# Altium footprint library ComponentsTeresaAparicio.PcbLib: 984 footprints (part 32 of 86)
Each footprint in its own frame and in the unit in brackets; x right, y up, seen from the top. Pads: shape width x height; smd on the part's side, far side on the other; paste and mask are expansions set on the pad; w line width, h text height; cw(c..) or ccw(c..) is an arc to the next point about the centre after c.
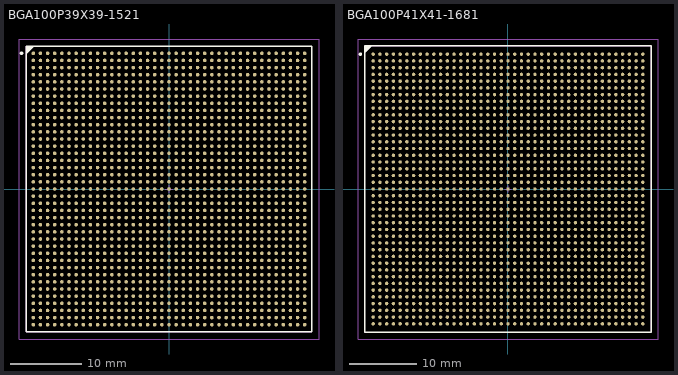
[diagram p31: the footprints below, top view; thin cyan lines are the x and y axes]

## BGA100P39X39-1521 [mm] "BGA, 1521-Leads, Body 40x40mm, Pitch 1mm"
height 3.5
pads (1521):
  round 0.5 smd: A1(-19,19) A2(-18,19) A3(-17,19) A4(-16,19) A5(-15,19) A6(-14,19) A7(-13,19) A8(-12,19) A9(-11,19) A10(-10,19) A11(-9,19) A12(-8,19) A13(-7,19) A14(-6,19) A15(-5,19) A16(-4,19) A17(-3,19) A18(-2,19) A19(-1,19) A20(0,19) A21(1,19) A22(2,19) A23(3,19) A24(4,19) A25(5,19) A26(6,19) A27(7,19) A28(8,19) A29(9,19) A30(10,19) A31(11,19) A32(12,19) A33(13,19) A34(14,19) A35(15,19) A36(16,19) A37(17,19) A38(18,19) A39(19,19) AA1(-19,-1) AA2(-18,-1) AA3(-17,-1) AA4(-16,-1) AA5(-15,-1) AA6(-14,-1) AA7(-13,-1) AA8(-12,-1) AA9(-11,-1) AA10(-10,-1) AA11(-9,-1) AA12(-8,-1) AA13(-7,-1) AA14(-6,-1) AA15(-5,-1) AA16(-4,-1) AA17(-3,-1) AA18(-2,-1) AA19(-1,-1) AA20(0,-1) AA21(1,-1) AA22(2,-1) AA23(3,-1) AA24(4,-1) AA25(5,-1) AA26(6,-1) AA27(7,-1) AA28(8,-1) AA29(9,-1) AA30(10,-1) AA31(11,-1) AA32(12,-1) AA33(13,-1) AA34(14,-1) AA35(15,-1) AA36(16,-1) AA37(17,-1) AA38(18,-1) AA39(19,-1) AB1(-19,-2) AB2(-18,-2) AB3(-17,-2) AB4(-16,-2) AB5(-15,-2) AB6(-14,-2) AB7(-13,-2) AB8(-12,-2) AB9(-11,-2) AB10(-10,-2) AB11(-9,-2) AB12(-8,-2) AB13(-7,-2) AB14(-6,-2) AB15(-5,-2) AB16(-4,-2) AB17(-3,-2) AB18(-2,-2) AB19(-1,-2) AB20(0,-2) AB21(1,-2) AB22(2,-2) AB23(3,-2) AB24(4,-2) AB25(5,-2) AB26(6,-2) AB27(7,-2) AB28(8,-2) AB29(9,-2) AB30(10,-2) AB31(11,-2) AB32(12,-2) AB33(13,-2) AB34(14,-2) AB35(15,-2) AB36(16,-2) AB37(17,-2) AB38(18,-2) AB39(19,-2) AC1(-19,-3) AC2(-18,-3) AC3(-17,-3) AC4(-16,-3) AC5(-15,-3) AC6(-14,-3) AC7(-13,-3) AC8(-12,-3) AC9(-11,-3) AC10(-10,-3) AC11(-9,-3) AC12(-8,-3) AC13(-7,-3) AC14(-6,-3) AC15(-5,-3) AC16(-4,-3) AC17(-3,-3) AC18(-2,-3) AC19(-1,-3) AC20(0,-3) AC21(1,-3) AC22(2,-3) AC23(3,-3) AC24(4,-3) AC25(5,-3) AC26(6,-3) AC27(7,-3) AC28(8,-3) AC29(9,-3) AC30(10,-3) AC31(11,-3) AC32(12,-3) AC33(13,-3) AC34(14,-3) AC35(15,-3) AC36(16,-3) AC37(17,-3) AC38(18,-3) AC39(19,-3) AD1(-19,-4) AD2(-18,-4) AD3(-17,-4) AD4(-16,-4) AD5(-15,-4) AD6(-14,-4) AD7(-13,-4) AD8(-12,-4) AD9(-11,-4) AD10(-10,-4) AD11(-9,-4) AD12(-8,-4) AD13(-7,-4) AD14(-6,-4) AD15(-5,-4) AD16(-4,-4) AD17(-3,-4) AD18(-2,-4) AD19(-1,-4) AD20(0,-4) AD21(1,-4) AD22(2,-4) AD23(3,-4) AD24(4,-4) AD25(5,-4) AD26(6,-4) AD27(7,-4) AD28(8,-4) AD29(9,-4) AD30(10,-4) AD31(11,-4) AD32(12,-4) AD33(13,-4) AD34(14,-4) AD35(15,-4) AD36(16,-4) AD37(17,-4) AD38(18,-4) AD39(19,-4) AE1(-19,-5) AE2(-18,-5) AE3(-17,-5) AE4(-16,-5) AE5(-15,-5) AE6(-14,-5) AE7(-13,-5) AE8(-12,-5) AE9(-11,-5) AE10(-10,-5) AE11(-9,-5) AE12(-8,-5) AE13(-7,-5) AE14(-6,-5) AE15(-5,-5) AE16(-4,-5) AE17(-3,-5) AE18(-2,-5) AE19(-1,-5) AE20(0,-5) AE21(1,-5) AE22(2,-5) AE23(3,-5) AE24(4,-5) AE25(5,-5) AE26(6,-5) AE27(7,-5) AE28(8,-5) AE29(9,-5) AE30(10,-5) AE31(11,-5) AE32(12,-5) AE33(13,-5) AE34(14,-5) AE35(15,-5) AE36(16,-5) AE37(17,-5) AE38(18,-5) AE39(19,-5) AF1(-19,-6) AF2(-18,-6) AF3(-17,-6) AF4(-16,-6) AF5(-15,-6) AF6(-14,-6) AF7(-13,-6) AF8(-12,-6) AF9(-11,-6) AF10(-10,-6) AF11(-9,-6) AF12(-8,-6) AF13(-7,-6) AF14(-6,-6) AF15(-5,-6) AF16(-4,-6) AF17(-3,-6) AF18(-2,-6) AF19(-1,-6) AF20(0,-6) AF21(1,-6) AF22(2,-6) AF23(3,-6) AF24(4,-6) AF25(5,-6) AF26(6,-6) AF27(7,-6) AF28(8,-6) AF29(9,-6) AF30(10,-6) AF31(11,-6) AF32(12,-6) AF33(13,-6) AF34(14,-6) AF35(15,-6) AF36(16,-6) AF37(17,-6) AF38(18,-6) AF39(19,-6) AG1(-19,-7) AG2(-18,-7) AG3(-17,-7) AG4(-16,-7) AG5(-15,-7) AG6(-14,-7) AG7(-13,-7) AG8(-12,-7) AG9(-11,-7) AG10(-10,-7) AG11(-9,-7) AG12(-8,-7) AG13(-7,-7) AG14(-6,-7) AG15(-5,-7) AG16(-4,-7) AG17(-3,-7) AG18(-2,-7) AG19(-1,-7) AG20(0,-7) AG21(1,-7) AG22(2,-7) AG23(3,-7) AG24(4,-7) AG25(5,-7) AG26(6,-7) AG27(7,-7) AG28(8,-7) AG29(9,-7) AG30(10,-7) AG31(11,-7) AG32(12,-7) AG33(13,-7) AG34(14,-7) AG35(15,-7) AG36(16,-7) AG37(17,-7) AG38(18,-7) AG39(19,-7) AH1(-19,-8) AH2(-18,-8) AH3(-17,-8) AH4(-16,-8) AH5(-15,-8) AH6(-14,-8) AH7(-13,-8) AH8(-12,-8) AH9(-11,-8) AH10(-10,-8) AH11(-9,-8) AH12(-8,-8) AH13(-7,-8) AH14(-6,-8) AH15(-5,-8) AH16(-4,-8) AH17(-3,-8) AH18(-2,-8) AH19(-1,-8) AH20(0,-8) AH21(1,-8) AH22(2,-8) AH23(3,-8) AH24(4,-8) AH25(5,-8) AH26(6,-8) AH27(7,-8) AH28(8,-8) AH29(9,-8) AH30(10,-8) AH31(11,-8) AH32(12,-8) AH33(13,-8) AH34(14,-8) AH35(15,-8) AH36(16,-8) AH37(17,-8) AH38(18,-8) AH39(19,-8) AJ1(-19,-9) AJ2(-18,-9) AJ3(-17,-9) AJ4(-16,-9) AJ5(-15,-9) AJ6(-14,-9) AJ7(-13,-9) AJ8(-12,-9) AJ9(-11,-9) AJ10(-10,-9) AJ11(-9,-9) AJ12(-8,-9) AJ13(-7,-9) AJ14(-6,-9) AJ15(-5,-9) AJ16(-4,-9) AJ17(-3,-9) AJ18(-2,-9) AJ19(-1,-9) AJ20(0,-9) AJ21(1,-9) AJ22(2,-9) AJ23(3,-9) AJ24(4,-9) AJ25(5,-9) AJ26(6,-9) AJ27(7,-9) AJ28(8,-9) AJ29(9,-9) AJ30(10,-9) AJ31(11,-9) AJ32(12,-9) AJ33(13,-9) AJ34(14,-9) AJ35(15,-9) AJ36(16,-9) AJ37(17,-9) AJ38(18,-9) AJ39(19,-9) AK1(-19,-10) AK2(-18,-10) AK3(-17,-10) AK4(-16,-10) AK5(-15,-10) AK6(-14,-10) AK7(-13,-10) AK8(-12,-10) AK9(-11,-10) AK10(-10,-10) AK11(-9,-10) AK12(-8,-10) AK13(-7,-10) AK14(-6,-10) AK15(-5,-10) AK16(-4,-10) AK17(-3,-10) AK18(-2,-10) AK19(-1,-10) AK20(0,-10) AK21(1,-10) AK22(2,-10) AK23(3,-10) AK24(4,-10) AK25(5,-10) AK26(6,-10) AK27(7,-10) AK28(8,-10) AK29(9,-10) AK30(10,-10) AK31(11,-10) AK32(12,-10) AK33(13,-10) AK34(14,-10) AK35(15,-10) AK36(16,-10) AK37(17,-10) AK38(18,-10) AK39(19,-10) AL1(-19,-11) AL2(-18,-11) AL3(-17,-11) AL4(-16,-11) AL5(-15,-11) AL6(-14,-11) AL7(-13,-11) AL8(-12,-11) AL9(-11,-11) AL10(-10,-11) AL11(-9,-11) AL12(-8,-11) AL13(-7,-11) AL14(-6,-11) AL15(-5,-11) AL16(-4,-11) AL17(-3,-11) AL18(-2,-11) AL19(-1,-11) AL20(0,-11) AL21(1,-11) AL22(2,-11) AL23(3,-11) AL24(4,-11) AL25(5,-11) AL26(6,-11) AL27(7,-11) AL28(8,-11) AL29(9,-11) AL30(10,-11) AL31(11,-11) AL32(12,-11) AL33(13,-11) AL34(14,-11) AL35(15,-11) AL36(16,-11) AL37(17,-11) AL38(18,-11) AL39(19,-11) AM1(-19,-12) AM2(-18,-12) AM3(-17,-12) AM4(-16,-12) AM5(-15,-12) AM6(-14,-12) AM7(-13,-12) AM8(-12,-12) AM9(-11,-12) AM10(-10,-12) AM11(-9,-12) AM12(-8,-12) AM13(-7,-12) AM14(-6,-12) AM15(-5,-12) AM16(-4,-12) AM17(-3,-12) AM18(-2,-12) AM19(-1,-12) AM20(0,-12) AM21(1,-12) AM22(2,-12) AM23(3,-12) AM24(4,-12) AM25(5,-12) AM26(6,-12) AM27(7,-12) AM28(8,-12) AM29(9,-12) AM30(10,-12) AM31(11,-12) AM32(12,-12) AM33(13,-12) AM34(14,-12) AM35(15,-12) AM36(16,-12) AM37(17,-12) AM38(18,-12) AM39(19,-12) AN1(-19,-13) AN2(-18,-13) AN3(-17,-13) AN4(-16,-13) AN5(-15,-13) AN6(-14,-13) AN7(-13,-13) AN8(-12,-13) AN9(-11,-13) AN10(-10,-13) AN11(-9,-13) AN12(-8,-13) AN13(-7,-13) AN14(-6,-13) AN15(-5,-13) AN16(-4,-13) AN17(-3,-13) AN18(-2,-13) AN19(-1,-13) AN20(0,-13) AN21(1,-13) AN22(2,-13) AN23(3,-13) AN24(4,-13) AN25(5,-13) AN26(6,-13) AN27(7,-13) AN28(8,-13) AN29(9,-13) AN30(10,-13) AN31(11,-13) AN32(12,-13) AN33(13,-13) AN34(14,-13) AN35(15,-13) AN36(16,-13) AN37(17,-13) AN38(18,-13) AN39(19,-13) AP1(-19,-14) AP2(-18,-14) AP3(-17,-14) AP4(-16,-14) AP5(-15,-14) AP6(-14,-14) AP7(-13,-14) AP8(-12,-14) AP9(-11,-14) AP10(-10,-14) AP11(-9,-14) AP12(-8,-14) AP13(-7,-14) AP14(-6,-14) AP15(-5,-14) AP16(-4,-14) AP17(-3,-14) AP18(-2,-14) AP19(-1,-14) AP20(0,-14) AP21(1,-14) AP22(2,-14) AP23(3,-14) AP24(4,-14) AP25(5,-14) AP26(6,-14) AP27(7,-14) AP28(8,-14) AP29(9,-14) AP30(10,-14) AP31(11,-14) AP32(12,-14) AP33(13,-14) AP34(14,-14) AP35(15,-14) AP36(16,-14) AP37(17,-14) AP38(18,-14) AP39(19,-14) AR1(-19,-15) AR2(-18,-15) AR3(-17,-15) AR4(-16,-15) AR5(-15,-15) AR6(-14,-15) AR7(-13,-15) AR8(-12,-15) AR9(-11,-15) AR10(-10,-15) AR11(-9,-15) AR12(-8,-15) AR13(-7,-15) AR14(-6,-15) AR15(-5,-15) AR16(-4,-15) AR17(-3,-15) AR18(-2,-15) AR19(-1,-15) AR20(0,-15) AR21(1,-15) AR22(2,-15) AR23(3,-15) AR24(4,-15) AR25(5,-15) AR26(6,-15) AR27(7,-15) AR28(8,-15) AR29(9,-15) AR30(10,-15) AR31(11,-15) AR32(12,-15) AR33(13,-15) AR34(14,-15) AR35(15,-15) AR36(16,-15) AR37(17,-15) AR38(18,-15) AR39(19,-15) AT1(-19,-16) AT2(-18,-16) AT3(-17,-16) AT4(-16,-16) AT5(-15,-16) AT6(-14,-16) AT7(-13,-16) AT8(-12,-16) AT9(-11,-16) AT10(-10,-16) AT11(-9,-16) AT12(-8,-16) AT13(-7,-16) AT14(-6,-16) AT15(-5,-16) AT16(-4,-16) AT17(-3,-16) AT18(-2,-16) AT19(-1,-16) AT20(0,-16) AT21(1,-16) AT22(2,-16) AT23(3,-16) AT24(4,-16) AT25(5,-16) AT26(6,-16) AT27(7,-16) AT28(8,-16) AT29(9,-16) AT30(10,-16) AT31(11,-16) AT32(12,-16) AT33(13,-16) AT34(14,-16) AT35(15,-16) AT36(16,-16) AT37(17,-16) AT38(18,-16) AT39(19,-16) AU1(-19,-17) AU2(-18,-17) AU3(-17,-17) AU4(-16,-17) AU5(-15,-17) AU6(-14,-17) AU7(-13,-17) AU8(-12,-17) AU9(-11,-17) AU10(-10,-17) AU11(-9,-17) AU12(-8,-17) AU13(-7,-17) AU14(-6,-17) AU15(-5,-17) AU16(-4,-17) AU17(-3,-17) AU18(-2,-17) AU19(-1,-17) AU20(0,-17) AU21(1,-17) AU22(2,-17) AU23(3,-17) AU24(4,-17) AU25(5,-17) AU26(6,-17) AU27(7,-17) AU28(8,-17) AU29(9,-17) AU30(10,-17) AU31(11,-17) AU32(12,-17) AU33(13,-17) AU34(14,-17) AU35(15,-17) AU36(16,-17) AU37(17,-17) AU38(18,-17) AU39(19,-17) AV1(-19,-18) AV2(-18,-18) AV3(-17,-18) AV4(-16,-18) AV5(-15,-18) AV6(-14,-18) AV7(-13,-18) AV8(-12,-18) AV9(-11,-18) AV10(-10,-18) AV11(-9,-18) AV12(-8,-18) AV13(-7,-18) AV14(-6,-18) AV15(-5,-18) AV16(-4,-18) AV17(-3,-18) AV18(-2,-18) AV19(-1,-18) AV20(0,-18) AV21(1,-18) AV22(2,-18) AV23(3,-18) AV24(4,-18) AV25(5,-18) AV26(6,-18) AV27(7,-18) AV28(8,-18) AV29(9,-18) AV30(10,-18) AV31(11,-18) AV32(12,-18) AV33(13,-18) AV34(14,-18) AV35(15,-18) AV36(16,-18) AV37(17,-18) AV38(18,-18) AV39(19,-18) AW1(-19,-19) AW2(-18,-19) AW3(-17,-19) AW4(-16,-19) AW5(-15,-19) AW6(-14,-19) AW7(-13,-19) AW8(-12,-19) AW9(-11,-19) AW10(-10,-19) AW11(-9,-19) AW12(-8,-19) AW13(-7,-19) AW14(-6,-19) AW15(-5,-19) AW16(-4,-19) AW17(-3,-19) AW18(-2,-19) AW19(-1,-19) AW20(0,-19) AW21(1,-19) AW22(2,-19) AW23(3,-19) AW24(4,-19) AW25(5,-19) AW26(6,-19) AW27(7,-19) AW28(8,-19) AW29(9,-19) AW30(10,-19) AW31(11,-19) AW32(12,-19) AW33(13,-19) AW34(14,-19) AW35(15,-19) AW36(16,-19) AW37(17,-19) AW38(18,-19) AW39(19,-19) B1(-19,18) B2(-18,18) B3(-17,18) B4(-16,18) B5(-15,18) B6(-14,18) B7(-13,18) B8(-12,18) B9(-11,18) B10(-10,18) B11(-9,18) B12(-8,18) B13(-7,18) B14(-6,18) B15(-5,18) B16(-4,18) B17(-3,18) B18(-2,18) B19(-1,18) B20(0,18) B21(1,18) B22(2,18) B23(3,18) B24(4,18) B25(5,18) B26(6,18) B27(7,18) B28(8,18) B29(9,18) B30(10,18) B31(11,18) B32(12,18) B33(13,18) B34(14,18) B35(15,18) B36(16,18) B37(17,18) B38(18,18) B39(19,18) C1(-19,17) C2(-18,17) C3(-17,17) C4(-16,17) C5(-15,17) C6(-14,17) C7(-13,17) C8(-12,17) C9(-11,17) C10(-10,17) C11(-9,17) C12(-8,17) C13(-7,17) C14(-6,17) C15(-5,17) C16(-4,17) C17(-3,17) C18(-2,17) C19(-1,17) C20(0,17) C21(1,17) C22(2,17) C23(3,17) C24(4,17) C25(5,17) C26(6,17) C27(7,17) C28(8,17) C29(9,17) C30(10,17) C31(11,17) C32(12,17) C33(13,17) C34(14,17) C35(15,17) C36(16,17) C37(17,17) C38(18,17) C39(19,17) D1(-19,16) D2(-18,16) D3(-17,16) D4(-16,16) D5(-15,16) D6(-14,16) D7(-13,16) D8(-12,16) D9(-11,16) D10(-10,16) D11(-9,16) D12(-8,16) D13(-7,16) D14(-6,16) D15(-5,16) D16(-4,16) D17(-3,16) D18(-2,16) D19(-1,16) D20(0,16) D21(1,16) D22(2,16) D23(3,16) D24(4,16) D25(5,16) D26(6,16) D27(7,16) D28(8,16) D29(9,16) D30(10,16) D31(11,16) D32(12,16) D33(13,16) D34(14,16) D35(15,16) D36(16,16) D37(17,16) D38(18,16) D39(19,16) E1(-19,15) E2(-18,15) E3(-17,15) E4(-16,15) E5(-15,15) E6(-14,15) E7(-13,15) E8(-12,15) E9(-11,15) E10(-10,15) E11(-9,15) E12(-8,15) E13(-7,15) E14(-6,15) E15(-5,15) E16(-4,15) E17(-3,15) E18(-2,15) E19(-1,15) E20(0,15) E21(1,15) E22(2,15) E23(3,15) E24(4,15) E25(5,15) E26(6,15) E27(7,15) E28(8,15) E29(9,15) E30(10,15) E31(11,15) E32(12,15) E33(13,15) E34(14,15) E35(15,15) E36(16,15) E37(17,15) E38(18,15) E39(19,15) F1(-19,14) F2(-18,14) F3(-17,14) F4(-16,14) F5(-15,14) F6(-14,14) F7(-13,14) F8(-12,14) F9(-11,14) F10(-10,14) F11(-9,14) F12(-8,14) F13(-7,14) F14(-6,14) F15(-5,14) F16(-4,14) F17(-3,14) F18(-2,14) F19(-1,14) F20(0,14) F21(1,14) F22(2,14) F23(3,14) F24(4,14) F25(5,14) F26(6,14) F27(7,14) F28(8,14) F29(9,14) F30(10,14) F31(11,14) F32(12,14) F33(13,14) F34(14,14) F35(15,14) F36(16,14) F37(17,14) F38(18,14) F39(19,14) G1(-19,13) G2(-18,13) G3(-17,13) G4(-16,13) G5(-15,13) G6(-14,13) G7(-13,13) G8(-12,13) G9(-11,13) G10(-10,13) G11(-9,13) G12(-8,13) G13(-7,13) G14(-6,13) G15(-5,13) G16(-4,13) G17(-3,13) G18(-2,13) G19(-1,13) G20(0,13) G21(1,13) G22(2,13) G23(3,13) G24(4,13) G25(5,13) G26(6,13) G27(7,13) G28(8,13) G29(9,13) G30(10,13) G31(11,13) G32(12,13) G33(13,13) G34(14,13) G35(15,13) G36(16,13) G37(17,13) G38(18,13) G39(19,13) H1(-19,12) H2(-18,12) H3(-17,12) H4(-16,12) H5(-15,12) H6(-14,12) H7(-13,12) H8(-12,12) H9(-11,12) H10(-10,12) H11(-9,12) H12(-8,12) H13(-7,12) H14(-6,12) H15(-5,12) H16(-4,12) H17(-3,12) H18(-2,12) H19(-1,12) H20(0,12) H21(1,12) H22(2,12) H23(3,12) H24(4,12) H25(5,12) H26(6,12) H27(7,12) H28(8,12) H29(9,12) H30(10,12) H31(11,12) H32(12,12) H33(13,12) H34(14,12) H35(15,12) H36(16,12) H37(17,12) H38(18,12) H39(19,12) J1(-19,11) J2(-18,11) J3(-17,11) J4(-16,11) J5(-15,11) J6(-14,11) J7(-13,11) J8(-12,11) J9(-11,11) J10(-10,11) J11(-9,11) J12(-8,11) J13(-7,11) J14(-6,11) J15(-5,11) J16(-4,11) J17(-3,11) J18(-2,11) J19(-1,11) J20(0,11) J21(1,11) J22(2,11) J23(3,11) J24(4,11) J25(5,11) J26(6,11) J27(7,11) J28(8,11) J29(9,11) J30(10,11) J31(11,11) J32(12,11) J33(13,11) J34(14,11) J35(15,11) J36(16,11) J37(17,11) J38(18,11) J39(19,11) K1(-19,10) K2(-18,10) K3(-17,10) K4(-16,10) K5(-15,10) K6(-14,10) K7(-13,10) K8(-12,10) K9(-11,10) K10(-10,10) K11(-9,10) K12(-8,10) K13(-7,10) K14(-6,10) K15(-5,10) K16(-4,10) K17(-3,10) K18(-2,10) K19(-1,10) K20(0,10) K21(1,10) K22(2,10) K23(3,10) K24(4,10) K25(5,10) K26(6,10) K27(7,10) K28(8,10) K29(9,10) K30(10,10) K31(11,10) K32(12,10) K33(13,10) K34(14,10) K35(15,10) K36(16,10) K37(17,10) K38(18,10) K39(19,10) L1(-19,9) L2(-18,9) L3(-17,9) L4(-16,9) L5(-15,9) L6(-14,9) L7(-13,9) L8(-12,9) L9(-11,9) L10(-10,9) L11(-9,9) L12(-8,9) L13(-7,9) L14(-6,9) L15(-5,9) L16(-4,9) L17(-3,9) L18(-2,9) L19(-1,9) L20(0,9) L21(1,9) L22(2,9) L23(3,9) L24(4,9) L25(5,9) L26(6,9) L27(7,9) L28(8,9) L29(9,9) L30(10,9) L31(11,9) L32(12,9) L33(13,9) L34(14,9) L35(15,9) L36(16,9) L37(17,9) L38(18,9) L39(19,9) M1(-19,8) M2(-18,8) M3(-17,8) M4(-16,8) M5(-15,8) M6(-14,8) M7(-13,8) M8(-12,8) M9(-11,8) M10(-10,8) M11(-9,8) M12(-8,8) M13(-7,8) M14(-6,8) M15(-5,8) M16(-4,8) M17(-3,8) M18(-2,8) M19(-1,8) M20(0,8) M21(1,8) M22(2,8) M23(3,8) M24(4,8) M25(5,8) M26(6,8) M27(7,8) M28(8,8) M29(9,8) M30(10,8) M31(11,8) M32(12,8) M33(13,8) M34(14,8) M35(15,8) M36(16,8) M37(17,8) M38(18,8) M39(19,8) N1(-19,7) N2(-18,7) N3(-17,7) N4(-16,7) N5(-15,7) N6(-14,7) N7(-13,7) N8(-12,7) N9(-11,7) N10(-10,7) N11(-9,7) N12(-8,7) N13(-7,7) N14(-6,7) N15(-5,7) N16(-4,7) N17(-3,7) N18(-2,7) N19(-1,7) N20(0,7) N21(1,7) N22(2,7) N23(3,7) N24(4,7) N25(5,7) N26(6,7) N27(7,7) N28(8,7) N29(9,7) N30(10,7) N31(11,7) N32(12,7) N33(13,7) N34(14,7) N35(15,7) N36(16,7) N37(17,7) N38(18,7) N39(19,7) P1(-19,6) P2(-18,6) P3(-17,6) P4(-16,6) P5(-15,6) P6(-14,6) P7(-13,6) P8(-12,6) P9(-11,6) P10(-10,6) P11(-9,6) P12(-8,6) P13(-7,6) P14(-6,6) P15(-5,6) P16(-4,6) P17(-3,6) P18(-2,6) P19(-1,6) P20(0,6) P21(1,6) P22(2,6) P23(3,6) P24(4,6) P25(5,6) P26(6,6) P27(7,6) P28(8,6) P29(9,6) P30(10,6) P31(11,6) P32(12,6) P33(13,6) P34(14,6) P35(15,6) P36(16,6) P37(17,6) P38(18,6) P39(19,6) R1(-19,5) R2(-18,5) R3(-17,5) R4(-16,5) R5(-15,5) R6(-14,5) R7(-13,5) R8(-12,5) R9(-11,5) R10(-10,5) R11(-9,5) R12(-8,5) R13(-7,5) R14(-6,5) R15(-5,5) R16(-4,5) R17(-3,5) R18(-2,5) R19(-1,5) R20(0,5) R21(1,5) R22(2,5) R23(3,5) R24(4,5) R25(5,5) R26(6,5) R27(7,5) R28(8,5) R29(9,5) R30(10,5) R31(11,5) R32(12,5) R33(13,5) R34(14,5) R35(15,5) R36(16,5) R37(17,5) R38(18,5) R39(19,5) T1(-19,4) T2(-18,4) T3(-17,4) T4(-16,4) T5(-15,4) T6(-14,4) T7(-13,4) T8(-12,4) T9(-11,4) T10(-10,4) T11(-9,4) T12(-8,4) T13(-7,4) T14(-6,4) T15(-5,4) T16(-4,4) T17(-3,4) T18(-2,4) T19(-1,4) T20(0,4) T21(1,4) T22(2,4) T23(3,4) T24(4,4) T25(5,4) T26(6,4) T27(7,4) T28(8,4) T29(9,4) T30(10,4) T31(11,4) T32(12,4) T33(13,4) T34(14,4) T35(15,4) T36(16,4) T37(17,4) T38(18,4) T39(19,4) U1(-19,3) U2(-18,3) U3(-17,3) U4(-16,3) U5(-15,3) U6(-14,3) U7(-13,3) U8(-12,3) U9(-11,3) U10(-10,3) U11(-9,3) U12(-8,3) U13(-7,3) U14(-6,3) U15(-5,3) U16(-4,3) U17(-3,3) U18(-2,3) U19(-1,3) U20(0,3) U21(1,3) U22(2,3) U23(3,3) U24(4,3) U25(5,3) U26(6,3) U27(7,3) U28(8,3) U29(9,3) U30(10,3) U31(11,3) U32(12,3) U33(13,3) U34(14,3) U35(15,3) U36(16,3) U37(17,3) U38(18,3) U39(19,3) V1(-19,2) V2(-18,2) V3(-17,2) V4(-16,2) V5(-15,2) V6(-14,2) V7(-13,2) V8(-12,2) V9(-11,2) V10(-10,2) V11(-9,2) V12(-8,2) V13(-7,2) V14(-6,2) V15(-5,2) V16(-4,2) V17(-3,2) V18(-2,2) V19(-1,2) V20(0,2) V21(1,2) V22(2,2) V23(3,2) V24(4,2) V25(5,2) V26(6,2) V27(7,2) V28(8,2) V29(9,2) V30(10,2) V31(11,2) V32(12,2) V33(13,2) V34(14,2) V35(15,2) V36(16,2) V37(17,2) V38(18,2) V39(19,2) W1(-19,1) W2(-18,1) W3(-17,1) W4(-16,1) W5(-15,1) W6(-14,1) W7(-13,1) W8(-12,1) W9(-11,1) W10(-10,1) W11(-9,1) W12(-8,1) W13(-7,1) W14(-6,1) W15(-5,1) W16(-4,1) W17(-3,1) W18(-2,1) W19(-1,1) W20(0,1) W21(1,1) W22(2,1) W23(3,1) W24(4,1) W25(5,1) W26(6,1) W27(7,1) W28(8,1) W29(9,1) W30(10,1) W31(11,1) W32(12,1) W33(13,1) W34(14,1) W35(15,1) W36(16,1) W37(17,1) W38(18,1) W39(19,1) Y1(-19,0) Y2(-18,0) Y3(-17,0) Y4(-16,0) Y5(-15,0) Y6(-14,0) Y7(-13,0) Y8(-12,0) Y9(-11,0) Y10(-10,0) Y11(-9,0) Y12(-8,0) Y13(-7,0) Y14(-6,0) Y15(-5,0) Y16(-4,0) Y17(-3,0) Y18(-2,0) Y19(-1,0) Y20(0,0) Y21(1,0) Y22(2,0) Y23(3,0) Y24(4,0) Y25(5,0) Y26(6,0) Y27(7,0) Y28(8,0) Y29(9,0) Y30(10,0) Y31(11,0) Y32(12,0) Y33(13,0) Y34(14,0) Y35(15,0) Y36(16,0) Y37(17,0) Y38(18,0) Y39(19,0)
Top Overlay:
  circle w0.25: c-20.65,19 r0.125
  region: -19,20 -20,19 -20,20
  lines w0.2: -20,19 -19,20 ; -20,-20 -20,20 20,20 20,-20 -20,-20
Mechanical 13:
  lines w0.1: -20,-20 -20,20 20,20 20,-20 -20,-20
Mechanical 15:
  lines w0.1: -0.5,0 0.5,0 ; 0,-0.5 0,0.5 ; -21,-21 -21,21 21,21 21,-21 -21,-21
3D body: height 0, standoff 0, extent -20,-20 20,20

## BGA100P41X41-1681 [mm] "BGA, 1681-Leads, Body 42.5x42.5mm, Pitch 1mm"
height 3.5
pads (1681):
  round 0.5 smd: A1(-20,20) A2(-19,20) A3(-18,20) A4(-17,20) A5(-16,20) A6(-15,20) A7(-14,20) A8(-13,20) A9(-12,20) A10(-11,20) A11(-10,20) A12(-9,20) A13(-8,20) A14(-7,20) A15(-6,20) A16(-5,20) A17(-4,20) A18(-3,20) A19(-2,20) A20(-1,20) A21(0,20) A22(1,20) A23(2,20) A24(3,20) A25(4,20) A26(5,20) A27(6,20) A28(7,20) A29(8,20) A30(9,20) A31(10,20) A32(11,20) A33(12,20) A34(13,20) A35(14,20) A36(15,20) A37(16,20) A38(17,20) A39(18,20) A40(19,20) A41(20,20) AA1(-20,0) AA2(-19,0) AA3(-18,0) AA4(-17,0) AA5(-16,0) AA6(-15,0) AA7(-14,0) AA8(-13,0) AA9(-12,0) AA10(-11,0) AA11(-10,0) AA12(-9,0) AA13(-8,0) AA14(-7,0) AA15(-6,0) AA16(-5,0) AA17(-4,0) AA18(-3,0) AA19(-2,0) AA20(-1,0) AA21(0,0) AA22(1,0) AA23(2,0) AA24(3,0) AA25(4,0) AA26(5,0) AA27(6,0) AA28(7,0) AA29(8,0) AA30(9,0) AA31(10,0) AA32(11,0) AA33(12,0) AA34(13,0) AA35(14,0) AA36(15,0) AA37(16,0) AA38(17,0) AA39(18,0) AA40(19,0) AA41(20,0) AB1(-20,-1) AB2(-19,-1) AB3(-18,-1) AB4(-17,-1) AB5(-16,-1) AB6(-15,-1) AB7(-14,-1) AB8(-13,-1) AB9(-12,-1) AB10(-11,-1) AB11(-10,-1) AB12(-9,-1) AB13(-8,-1) AB14(-7,-1) AB15(-6,-1) AB16(-5,-1) AB17(-4,-1) AB18(-3,-1) AB19(-2,-1) AB20(-1,-1) AB21(0,-1) AB22(1,-1) AB23(2,-1) AB24(3,-1) AB25(4,-1) AB26(5,-1) AB27(6,-1) AB28(7,-1) AB29(8,-1) AB30(9,-1) AB31(10,-1) AB32(11,-1) AB33(12,-1) AB34(13,-1) AB35(14,-1) AB36(15,-1) AB37(16,-1) AB38(17,-1) AB39(18,-1) AB40(19,-1) AB41(20,-1) AC1(-20,-2) AC2(-19,-2) AC3(-18,-2) AC4(-17,-2) AC5(-16,-2) AC6(-15,-2) AC7(-14,-2) AC8(-13,-2) AC9(-12,-2) AC10(-11,-2) AC11(-10,-2) AC12(-9,-2) AC13(-8,-2) AC14(-7,-2) AC15(-6,-2) AC16(-5,-2) AC17(-4,-2) AC18(-3,-2) AC19(-2,-2) AC20(-1,-2) AC21(0,-2) AC22(1,-2) AC23(2,-2) AC24(3,-2) AC25(4,-2) AC26(5,-2) AC27(6,-2) AC28(7,-2) AC29(8,-2) AC30(9,-2) AC31(10,-2) AC32(11,-2) AC33(12,-2) AC34(13,-2) AC35(14,-2) AC36(15,-2) AC37(16,-2) AC38(17,-2) AC39(18,-2) AC40(19,-2) AC41(20,-2) AD1(-20,-3) AD2(-19,-3) AD3(-18,-3) AD4(-17,-3) AD5(-16,-3) AD6(-15,-3) AD7(-14,-3) AD8(-13,-3) AD9(-12,-3) AD10(-11,-3) AD11(-10,-3) AD12(-9,-3) AD13(-8,-3) AD14(-7,-3) AD15(-6,-3) AD16(-5,-3) AD17(-4,-3) AD18(-3,-3) AD19(-2,-3) AD20(-1,-3) AD21(0,-3) AD22(1,-3) AD23(2,-3) AD24(3,-3) AD25(4,-3) AD26(5,-3) AD27(6,-3) AD28(7,-3) AD29(8,-3) AD30(9,-3) AD31(10,-3) AD32(11,-3) AD33(12,-3) AD34(13,-3) AD35(14,-3) AD36(15,-3) AD37(16,-3) AD38(17,-3) AD39(18,-3) AD40(19,-3) AD41(20,-3) AE1(-20,-4) AE2(-19,-4) AE3(-18,-4) AE4(-17,-4) AE5(-16,-4) AE6(-15,-4) AE7(-14,-4) AE8(-13,-4) AE9(-12,-4) AE10(-11,-4) AE11(-10,-4) AE12(-9,-4) AE13(-8,-4) AE14(-7,-4) AE15(-6,-4) AE16(-5,-4) AE17(-4,-4) AE18(-3,-4) AE19(-2,-4) AE20(-1,-4) AE21(0,-4) AE22(1,-4) AE23(2,-4) AE24(3,-4) AE25(4,-4) AE26(5,-4) AE27(6,-4) AE28(7,-4) AE29(8,-4) AE30(9,-4) AE31(10,-4) AE32(11,-4) AE33(12,-4) AE34(13,-4) AE35(14,-4) AE36(15,-4) AE37(16,-4) AE38(17,-4) AE39(18,-4) AE40(19,-4) AE41(20,-4) AF1(-20,-5) AF2(-19,-5) AF3(-18,-5) AF4(-17,-5) AF5(-16,-5) AF6(-15,-5) AF7(-14,-5) AF8(-13,-5) AF9(-12,-5) AF10(-11,-5) AF11(-10,-5) AF12(-9,-5) AF13(-8,-5) AF14(-7,-5) AF15(-6,-5) AF16(-5,-5) AF17(-4,-5) AF18(-3,-5) AF19(-2,-5) AF20(-1,-5) AF21(0,-5) AF22(1,-5) AF23(2,-5) AF24(3,-5) AF25(4,-5) AF26(5,-5) AF27(6,-5) AF28(7,-5) AF29(8,-5) AF30(9,-5) AF31(10,-5) AF32(11,-5) AF33(12,-5) AF34(13,-5) AF35(14,-5) AF36(15,-5) AF37(16,-5) AF38(17,-5) AF39(18,-5) AF40(19,-5) AF41(20,-5) AG1(-20,-6) AG2(-19,-6) AG3(-18,-6) AG4(-17,-6) AG5(-16,-6) AG6(-15,-6) AG7(-14,-6) AG8(-13,-6) AG9(-12,-6) AG10(-11,-6) AG11(-10,-6) AG12(-9,-6) AG13(-8,-6) AG14(-7,-6) AG15(-6,-6) AG16(-5,-6) AG17(-4,-6) AG18(-3,-6) AG19(-2,-6) AG20(-1,-6) AG21(0,-6) AG22(1,-6) AG23(2,-6) AG24(3,-6) AG25(4,-6) AG26(5,-6) AG27(6,-6) AG28(7,-6) AG29(8,-6) AG30(9,-6) AG31(10,-6) AG32(11,-6) AG33(12,-6) AG34(13,-6) AG35(14,-6) AG36(15,-6) AG37(16,-6) AG38(17,-6) AG39(18,-6) AG40(19,-6) AG41(20,-6) AH1(-20,-7) AH2(-19,-7) AH3(-18,-7) AH4(-17,-7) AH5(-16,-7) AH6(-15,-7) AH7(-14,-7) AH8(-13,-7) AH9(-12,-7) AH10(-11,-7) AH11(-10,-7) AH12(-9,-7) AH13(-8,-7) AH14(-7,-7) AH15(-6,-7) AH16(-5,-7) AH17(-4,-7) AH18(-3,-7) AH19(-2,-7) AH20(-1,-7) AH21(0,-7) AH22(1,-7) AH23(2,-7) AH24(3,-7) AH25(4,-7) AH26(5,-7) AH27(6,-7) AH28(7,-7) AH29(8,-7) AH30(9,-7) AH31(10,-7) AH32(11,-7) AH33(12,-7) AH34(13,-7) AH35(14,-7) AH36(15,-7) AH37(16,-7) AH38(17,-7) AH39(18,-7) AH40(19,-7) AH41(20,-7) AJ1(-20,-8) AJ2(-19,-8) AJ3(-18,-8) AJ4(-17,-8) AJ5(-16,-8) AJ6(-15,-8) AJ7(-14,-8) AJ8(-13,-8) AJ9(-12,-8) AJ10(-11,-8) AJ11(-10,-8) AJ12(-9,-8) AJ13(-8,-8) AJ14(-7,-8) AJ15(-6,-8) AJ16(-5,-8) AJ17(-4,-8) AJ18(-3,-8) AJ19(-2,-8) AJ20(-1,-8) AJ21(0,-8) AJ22(1,-8) AJ23(2,-8) AJ24(3,-8) AJ25(4,-8) AJ26(5,-8) AJ27(6,-8) AJ28(7,-8) AJ29(8,-8) AJ30(9,-8) AJ31(10,-8) AJ32(11,-8) AJ33(12,-8) AJ34(13,-8) AJ35(14,-8) AJ36(15,-8) AJ37(16,-8) AJ38(17,-8) AJ39(18,-8) AJ40(19,-8) AJ41(20,-8) AK1(-20,-9) AK2(-19,-9) AK3(-18,-9) AK4(-17,-9) AK5(-16,-9) AK6(-15,-9) AK7(-14,-9) AK8(-13,-9) AK9(-12,-9) AK10(-11,-9) AK11(-10,-9) AK12(-9,-9) AK13(-8,-9) AK14(-7,-9) AK15(-6,-9) AK16(-5,-9) AK17(-4,-9) AK18(-3,-9) AK19(-2,-9) AK20(-1,-9) AK21(0,-9) AK22(1,-9) AK23(2,-9) AK24(3,-9) AK25(4,-9) AK26(5,-9) AK27(6,-9) AK28(7,-9) AK29(8,-9) AK30(9,-9) AK31(10,-9) AK32(11,-9) AK33(12,-9) AK34(13,-9) AK35(14,-9) AK36(15,-9) AK37(16,-9) AK38(17,-9) AK39(18,-9) AK40(19,-9) AK41(20,-9) AL1(-20,-10) AL2(-19,-10) AL3(-18,-10) AL4(-17,-10) AL5(-16,-10) AL6(-15,-10) AL7(-14,-10) AL8(-13,-10) AL9(-12,-10) AL10(-11,-10) AL11(-10,-10) AL12(-9,-10) AL13(-8,-10) AL14(-7,-10) AL15(-6,-10) AL16(-5,-10) AL17(-4,-10) AL18(-3,-10) AL19(-2,-10) AL20(-1,-10) AL21(0,-10) AL22(1,-10) AL23(2,-10) AL24(3,-10) AL25(4,-10) AL26(5,-10) AL27(6,-10) AL28(7,-10) AL29(8,-10) AL30(9,-10) AL31(10,-10) AL32(11,-10) AL33(12,-10) AL34(13,-10) AL35(14,-10) AL36(15,-10) AL37(16,-10) AL38(17,-10) AL39(18,-10) AL40(19,-10) AL41(20,-10) AM1(-20,-11) AM2(-19,-11) AM3(-18,-11) AM4(-17,-11) AM5(-16,-11) AM6(-15,-11) AM7(-14,-11) AM8(-13,-11) AM9(-12,-11) AM10(-11,-11) AM11(-10,-11) AM12(-9,-11) AM13(-8,-11) AM14(-7,-11) AM15(-6,-11) AM16(-5,-11) AM17(-4,-11) AM18(-3,-11) AM19(-2,-11) AM20(-1,-11) AM21(0,-11) AM22(1,-11) AM23(2,-11) AM24(3,-11) AM25(4,-11) AM26(5,-11) AM27(6,-11) AM28(7,-11) AM29(8,-11) AM30(9,-11) AM31(10,-11) AM32(11,-11) AM33(12,-11) AM34(13,-11) AM35(14,-11) AM36(15,-11) AM37(16,-11) AM38(17,-11) AM39(18,-11) AM40(19,-11) AM41(20,-11) AN1(-20,-12) AN2(-19,-12) AN3(-18,-12) AN4(-17,-12) AN5(-16,-12) AN6(-15,-12) AN7(-14,-12) AN8(-13,-12) AN9(-12,-12) AN10(-11,-12) AN11(-10,-12) AN12(-9,-12) AN13(-8,-12) AN14(-7,-12) AN15(-6,-12) AN16(-5,-12) AN17(-4,-12) AN18(-3,-12) AN19(-2,-12) AN20(-1,-12) AN21(0,-12) AN22(1,-12) AN23(2,-12) AN24(3,-12) AN25(4,-12) AN26(5,-12) AN27(6,-12) AN28(7,-12) AN29(8,-12) AN30(9,-12) AN31(10,-12) AN32(11,-12) AN33(12,-12) AN34(13,-12) AN35(14,-12) AN36(15,-12) AN37(16,-12) AN38(17,-12) AN39(18,-12) AN40(19,-12) AN41(20,-12) AP1(-20,-13) AP2(-19,-13) AP3(-18,-13) AP4(-17,-13) AP5(-16,-13) AP6(-15,-13) AP7(-14,-13) AP8(-13,-13) AP9(-12,-13) AP10(-11,-13) AP11(-10,-13) AP12(-9,-13) AP13(-8,-13) AP14(-7,-13) AP15(-6,-13) AP16(-5,-13) AP17(-4,-13) AP18(-3,-13) AP19(-2,-13) AP20(-1,-13) AP21(0,-13) AP22(1,-13) AP23(2,-13) AP24(3,-13) AP25(4,-13) AP26(5,-13) AP27(6,-13) AP28(7,-13) AP29(8,-13) AP30(9,-13) AP31(10,-13) AP32(11,-13) AP33(12,-13) AP34(13,-13) AP35(14,-13) AP36(15,-13) AP37(16,-13) AP38(17,-13) AP39(18,-13) AP40(19,-13) AP41(20,-13) AR1(-20,-14) AR2(-19,-14) AR3(-18,-14) AR4(-17,-14) AR5(-16,-14) AR6(-15,-14) AR7(-14,-14) AR8(-13,-14) AR9(-12,-14) AR10(-11,-14) AR11(-10,-14) AR12(-9,-14) AR13(-8,-14) AR14(-7,-14) AR15(-6,-14) AR16(-5,-14) AR17(-4,-14) AR18(-3,-14) AR19(-2,-14) AR20(-1,-14) AR21(0,-14) AR22(1,-14) AR23(2,-14) AR24(3,-14) AR25(4,-14) AR26(5,-14) AR27(6,-14) AR28(7,-14) AR29(8,-14) AR30(9,-14) AR31(10,-14) AR32(11,-14) AR33(12,-14) AR34(13,-14) AR35(14,-14) AR36(15,-14) AR37(16,-14) AR38(17,-14) AR39(18,-14) AR40(19,-14) AR41(20,-14) AT1(-20,-15) AT2(-19,-15) AT3(-18,-15) AT4(-17,-15) AT5(-16,-15) AT6(-15,-15) AT7(-14,-15) AT8(-13,-15) AT9(-12,-15) AT10(-11,-15) AT11(-10,-15) AT12(-9,-15) AT13(-8,-15) AT14(-7,-15) AT15(-6,-15) AT16(-5,-15) AT17(-4,-15) AT18(-3,-15) AT19(-2,-15) AT20(-1,-15) AT21(0,-15) AT22(1,-15) AT23(2,-15) AT24(3,-15) AT25(4,-15) AT26(5,-15) AT27(6,-15) AT28(7,-15) AT29(8,-15) AT30(9,-15) AT31(10,-15) AT32(11,-15) AT33(12,-15) AT34(13,-15) AT35(14,-15) AT36(15,-15) AT37(16,-15) AT38(17,-15) AT39(18,-15) AT40(19,-15) AT41(20,-15) AU1(-20,-16) AU2(-19,-16) AU3(-18,-16) AU4(-17,-16) AU5(-16,-16) AU6(-15,-16) AU7(-14,-16) AU8(-13,-16) AU9(-12,-16) AU10(-11,-16) AU11(-10,-16) AU12(-9,-16) AU13(-8,-16) AU14(-7,-16) AU15(-6,-16) AU16(-5,-16) AU17(-4,-16) AU18(-3,-16) AU19(-2,-16) AU20(-1,-16) AU21(0,-16) AU22(1,-16) AU23(2,-16) AU24(3,-16) AU25(4,-16) AU26(5,-16) AU27(6,-16) AU28(7,-16) AU29(8,-16) AU30(9,-16) AU31(10,-16) AU32(11,-16) AU33(12,-16) AU34(13,-16) AU35(14,-16) AU36(15,-16) AU37(16,-16) AU38(17,-16) AU39(18,-16) AU40(19,-16) AU41(20,-16) AV1(-20,-17) AV2(-19,-17) AV3(-18,-17) AV4(-17,-17) AV5(-16,-17) AV6(-15,-17) AV7(-14,-17) AV8(-13,-17) AV9(-12,-17) AV10(-11,-17) AV11(-10,-17) AV12(-9,-17) AV13(-8,-17) AV14(-7,-17) AV15(-6,-17) AV16(-5,-17) AV17(-4,-17) AV18(-3,-17) AV19(-2,-17) AV20(-1,-17) AV21(0,-17) AV22(1,-17) AV23(2,-17) AV24(3,-17) AV25(4,-17) AV26(5,-17) AV27(6,-17) AV28(7,-17) AV29(8,-17) AV30(9,-17) AV31(10,-17) AV32(11,-17) AV33(12,-17) AV34(13,-17) AV35(14,-17) AV36(15,-17) AV37(16,-17) AV38(17,-17) AV39(18,-17) AV40(19,-17) AV41(20,-17) AW1(-20,-18) AW2(-19,-18) AW3(-18,-18) AW4(-17,-18) AW5(-16,-18) AW6(-15,-18) AW7(-14,-18) AW8(-13,-18) AW9(-12,-18) AW10(-11,-18) AW11(-10,-18) AW12(-9,-18) AW13(-8,-18) AW14(-7,-18) AW15(-6,-18) AW16(-5,-18) AW17(-4,-18) AW18(-3,-18) AW19(-2,-18) AW20(-1,-18) AW21(0,-18) AW22(1,-18) AW23(2,-18) AW24(3,-18) AW25(4,-18) AW26(5,-18) AW27(6,-18) AW28(7,-18) AW29(8,-18) AW30(9,-18) AW31(10,-18) AW32(11,-18) AW33(12,-18) AW34(13,-18) AW35(14,-18) AW36(15,-18) AW37(16,-18) AW38(17,-18) AW39(18,-18) AW40(19,-18) AW41(20,-18) AY1(-20,-19) AY2(-19,-19) AY3(-18,-19) AY4(-17,-19) AY5(-16,-19) AY6(-15,-19) AY7(-14,-19) AY8(-13,-19) AY9(-12,-19) AY10(-11,-19) AY11(-10,-19) AY12(-9,-19) AY13(-8,-19) AY14(-7,-19) AY15(-6,-19) AY16(-5,-19) AY17(-4,-19) AY18(-3,-19) AY19(-2,-19) AY20(-1,-19) AY21(0,-19) AY22(1,-19) AY23(2,-19) AY24(3,-19) AY25(4,-19) AY26(5,-19) AY27(6,-19) AY28(7,-19) AY29(8,-19) AY30(9,-19) AY31(10,-19) AY32(11,-19) AY33(12,-19) AY34(13,-19) AY35(14,-19) AY36(15,-19) AY37(16,-19) AY38(17,-19) AY39(18,-19) AY40(19,-19) AY41(20,-19) B1(-20,19) B2(-19,19) B3(-18,19) B4(-17,19) B5(-16,19) B6(-15,19) B7(-14,19) B8(-13,19) B9(-12,19) B10(-11,19) B11(-10,19) B12(-9,19) B13(-8,19) B14(-7,19) B15(-6,19) B16(-5,19) B17(-4,19) B18(-3,19) B19(-2,19) B20(-1,19) B21(0,19) B22(1,19) B23(2,19) B24(3,19) B25(4,19) B26(5,19) B27(6,19) B28(7,19) B29(8,19) B30(9,19) B31(10,19) B32(11,19) B33(12,19) B34(13,19) B35(14,19) B36(15,19) B37(16,19) B38(17,19) B39(18,19) B40(19,19) B41(20,19) BA1(-20,-20) BA2(-19,-20) BA3(-18,-20) BA4(-17,-20) BA5(-16,-20) BA6(-15,-20) BA7(-14,-20) BA8(-13,-20) BA9(-12,-20) BA10(-11,-20) BA11(-10,-20) BA12(-9,-20) BA13(-8,-20) BA14(-7,-20) BA15(-6,-20) BA16(-5,-20) BA17(-4,-20) BA18(-3,-20) BA19(-2,-20) BA20(-1,-20) BA21(0,-20) BA22(1,-20) BA23(2,-20) BA24(3,-20) BA25(4,-20) BA26(5,-20) BA27(6,-20) BA28(7,-20) BA29(8,-20) BA30(9,-20) BA31(10,-20) BA32(11,-20) BA33(12,-20) BA34(13,-20) BA35(14,-20) BA36(15,-20) BA37(16,-20) BA38(17,-20) BA39(18,-20) BA40(19,-20) BA41(20,-20) C1(-20,18) C2(-19,18) C3(-18,18) C4(-17,18) C5(-16,18) C6(-15,18) C7(-14,18) C8(-13,18) C9(-12,18) C10(-11,18) C11(-10,18) C12(-9,18) C13(-8,18) C14(-7,18) C15(-6,18) C16(-5,18) C17(-4,18) C18(-3,18) C19(-2,18) C20(-1,18) C21(0,18) C22(1,18) C23(2,18) C24(3,18) C25(4,18) C26(5,18) C27(6,18) C28(7,18) C29(8,18) C30(9,18) C31(10,18) C32(11,18) C33(12,18) C34(13,18) C35(14,18) C36(15,18) C37(16,18) C38(17,18) C39(18,18) C40(19,18) C41(20,18) D1(-20,17) D2(-19,17) D3(-18,17) D4(-17,17) D5(-16,17) D6(-15,17) D7(-14,17) D8(-13,17) D9(-12,17) D10(-11,17) D11(-10,17) D12(-9,17) D13(-8,17) D14(-7,17) D15(-6,17) D16(-5,17) D17(-4,17) D18(-3,17) D19(-2,17) D20(-1,17) D21(0,17) D22(1,17) D23(2,17) D24(3,17) D25(4,17) D26(5,17) D27(6,17) D28(7,17) D29(8,17) D30(9,17) D31(10,17) D32(11,17) D33(12,17) D34(13,17) D35(14,17) D36(15,17) D37(16,17) D38(17,17) D39(18,17) D40(19,17) D41(20,17) E1(-20,16) E2(-19,16) E3(-18,16) E4(-17,16) E5(-16,16) E6(-15,16) E7(-14,16) E8(-13,16) E9(-12,16) E10(-11,16) E11(-10,16) E12(-9,16) E13(-8,16) E14(-7,16) E15(-6,16) E16(-5,16) E17(-4,16) E18(-3,16) E19(-2,16) E20(-1,16) E21(0,16) E22(1,16) E23(2,16) E24(3,16) E25(4,16) E26(5,16) E27(6,16) E28(7,16) E29(8,16) E30(9,16) E31(10,16) E32(11,16) E33(12,16) E34(13,16) E35(14,16) E36(15,16) E37(16,16) E38(17,16) E39(18,16) E40(19,16) E41(20,16) F1(-20,15) F2(-19,15) F3(-18,15) F4(-17,15) F5(-16,15) F6(-15,15) F7(-14,15) F8(-13,15) F9(-12,15) F10(-11,15) F11(-10,15) F12(-9,15) F13(-8,15) F14(-7,15) F15(-6,15) F16(-5,15) F17(-4,15) F18(-3,15) F19(-2,15) F20(-1,15) F21(0,15) F22(1,15) F23(2,15) F24(3,15) F25(4,15) F26(5,15) F27(6,15) F28(7,15) F29(8,15) F30(9,15) F31(10,15) F32(11,15) F33(12,15) F34(13,15) F35(14,15) F36(15,15) F37(16,15) F38(17,15) F39(18,15) F40(19,15) F41(20,15) G1(-20,14) G2(-19,14) G3(-18,14) G4(-17,14) G5(-16,14) G6(-15,14) G7(-14,14) G8(-13,14) G9(-12,14) G10(-11,14) G11(-10,14) G12(-9,14) G13(-8,14) G14(-7,14) G15(-6,14) G16(-5,14) G17(-4,14) G18(-3,14) G19(-2,14) G20(-1,14) G21(0,14) G22(1,14) G23(2,14) G24(3,14) G25(4,14) G26(5,14) G27(6,14) G28(7,14) G29(8,14) G30(9,14) G31(10,14) G32(11,14) G33(12,14) G34(13,14) G35(14,14) G36(15,14) G37(16,14) G38(17,14) G39(18,14) G40(19,14) G41(20,14) H1(-20,13) H2(-19,13) H3(-18,13) H4(-17,13) H5(-16,13) H6(-15,13) H7(-14,13) H8(-13,13) H9(-12,13) H10(-11,13) H11(-10,13) H12(-9,13) H13(-8,13) H14(-7,13) H15(-6,13) H16(-5,13) H17(-4,13) H18(-3,13) H19(-2,13) H20(-1,13) H21(0,13) H22(1,13) H23(2,13) H24(3,13) H25(4,13) H26(5,13) H27(6,13) H28(7,13) H29(8,13) H30(9,13) H31(10,13) H32(11,13) H33(12,13) H34(13,13) H35(14,13) H36(15,13) H37(16,13) H38(17,13) H39(18,13) H40(19,13) H41(20,13) J1(-20,12) J2(-19,12) J3(-18,12) J4(-17,12) J5(-16,12) J6(-15,12) J7(-14,12) J8(-13,12) J9(-12,12) J10(-11,12) J11(-10,12) J12(-9,12) J13(-8,12) J14(-7,12) J15(-6,12) J16(-5,12) J17(-4,12) J18(-3,12) J19(-2,12) J20(-1,12) J21(0,12) J22(1,12) J23(2,12) J24(3,12) J25(4,12) J26(5,12) J27(6,12) J28(7,12) J29(8,12) J30(9,12) J31(10,12) J32(11,12) J33(12,12) J34(13,12) J35(14,12) J36(15,12) J37(16,12) J38(17,12) J39(18,12) J40(19,12) J41(20,12) K1(-20,11) K2(-19,11) K3(-18,11) K4(-17,11) K5(-16,11) K6(-15,11) K7(-14,11) K8(-13,11) K9(-12,11) K10(-11,11) K11(-10,11) K12(-9,11) K13(-8,11) K14(-7,11) K15(-6,11) K16(-5,11) K17(-4,11) K18(-3,11) K19(-2,11) K20(-1,11) K21(0,11) K22(1,11) K23(2,11) K24(3,11) K25(4,11) K26(5,11) K27(6,11) K28(7,11) K29(8,11) K30(9,11) K31(10,11) K32(11,11) K33(12,11) K34(13,11) K35(14,11) K36(15,11) K37(16,11) K38(17,11) K39(18,11) K40(19,11) K41(20,11) L1(-20,10) L2(-19,10) L3(-18,10) L4(-17,10) L5(-16,10) L6(-15,10) L7(-14,10) L8(-13,10) L9(-12,10) L10(-11,10) L11(-10,10) L12(-9,10) L13(-8,10) L14(-7,10) L15(-6,10) L16(-5,10) L17(-4,10) L18(-3,10) L19(-2,10) L20(-1,10) L21(0,10) L22(1,10) L23(2,10) L24(3,10) L25(4,10) L26(5,10) L27(6,10) L28(7,10) L29(8,10) L30(9,10) L31(10,10) L32(11,10) L33(12,10) L34(13,10) L35(14,10) L36(15,10) L37(16,10) L38(17,10) L39(18,10) L40(19,10) L41(20,10) M1(-20,9) M2(-19,9) M3(-18,9) M4(-17,9) M5(-16,9) M6(-15,9) M7(-14,9) M8(-13,9) M9(-12,9) M10(-11,9) M11(-10,9) M12(-9,9) M13(-8,9) M14(-7,9) M15(-6,9) M16(-5,9) M17(-4,9) M18(-3,9) M19(-2,9) M20(-1,9) M21(0,9) M22(1,9) M23(2,9) M24(3,9) M25(4,9) M26(5,9) M27(6,9) M28(7,9) M29(8,9) M30(9,9) M31(10,9) M32(11,9) M33(12,9) M34(13,9) M35(14,9) M36(15,9) M37(16,9) M38(17,9) M39(18,9) M40(19,9) M41(20,9) N1(-20,8) N2(-19,8) N3(-18,8) N4(-17,8) N5(-16,8) N6(-15,8) N7(-14,8) N8(-13,8) N9(-12,8) N10(-11,8) N11(-10,8) N12(-9,8) N13(-8,8) N14(-7,8) N15(-6,8) N16(-5,8) N17(-4,8) N18(-3,8) N19(-2,8) N20(-1,8) N21(0,8) N22(1,8) N23(2,8) N24(3,8) N25(4,8) N26(5,8) N27(6,8) N28(7,8) N29(8,8) N30(9,8) N31(10,8) N32(11,8) N33(12,8) N34(13,8) N35(14,8) N36(15,8) N37(16,8) N38(17,8) N39(18,8) N40(19,8) N41(20,8) P1(-20,7) P2(-19,7) P3(-18,7) P4(-17,7) P5(-16,7) P6(-15,7) P7(-14,7) P8(-13,7) P9(-12,7) P10(-11,7) P11(-10,7) P12(-9,7) P13(-8,7) P14(-7,7) P15(-6,7) P16(-5,7) P17(-4,7) P18(-3,7) P19(-2,7) P20(-1,7) P21(0,7) P22(1,7) P23(2,7) P24(3,7) P25(4,7) P26(5,7) P27(6,7) P28(7,7) P29(8,7) P30(9,7) P31(10,7) P32(11,7) P33(12,7) P34(13,7) P35(14,7) P36(15,7) P37(16,7) P38(17,7) P39(18,7) P40(19,7) P41(20,7) R1(-20,6) R2(-19,6) R3(-18,6) R4(-17,6) R5(-16,6) R6(-15,6) R7(-14,6) R8(-13,6) R9(-12,6) R10(-11,6) R11(-10,6) R12(-9,6) R13(-8,6) R14(-7,6) R15(-6,6) R16(-5,6) R17(-4,6) R18(-3,6) R19(-2,6) R20(-1,6) R21(0,6) R22(1,6) R23(2,6) R24(3,6) R25(4,6) R26(5,6) R27(6,6) R28(7,6) R29(8,6) R30(9,6) R31(10,6) R32(11,6) R33(12,6) R34(13,6) R35(14,6) R36(15,6) R37(16,6) R38(17,6) R39(18,6) R40(19,6) R41(20,6) T1(-20,5) T2(-19,5) T3(-18,5) T4(-17,5) T5(-16,5) T6(-15,5) T7(-14,5) T8(-13,5) T9(-12,5) T10(-11,5) T11(-10,5) T12(-9,5) T13(-8,5) T14(-7,5) T15(-6,5) T16(-5,5) T17(-4,5) T18(-3,5) T19(-2,5) T20(-1,5) T21(0,5) T22(1,5) T23(2,5) T24(3,5) T25(4,5) T26(5,5) T27(6,5) T28(7,5) T29(8,5) T30(9,5) T31(10,5) T32(11,5) T33(12,5) T34(13,5) T35(14,5) T36(15,5) T37(16,5) T38(17,5) T39(18,5) T40(19,5) T41(20,5) U1(-20,4) U2(-19,4) U3(-18,4) U4(-17,4) U5(-16,4) U6(-15,4) U7(-14,4) U8(-13,4) U9(-12,4) U10(-11,4) U11(-10,4) U12(-9,4) U13(-8,4) U14(-7,4) U15(-6,4) U16(-5,4) U17(-4,4) U18(-3,4) U19(-2,4) U20(-1,4) U21(0,4) U22(1,4) U23(2,4) U24(3,4) U25(4,4) U26(5,4) U27(6,4) U28(7,4) U29(8,4) U30(9,4) U31(10,4) U32(11,4) U33(12,4) U34(13,4) U35(14,4) U36(15,4) U37(16,4) U38(17,4) U39(18,4) U40(19,4) U41(20,4) V1(-20,3) V2(-19,3) V3(-18,3) V4(-17,3) V5(-16,3) V6(-15,3) V7(-14,3) V8(-13,3) V9(-12,3) V10(-11,3) V11(-10,3) V12(-9,3) V13(-8,3) V14(-7,3) V15(-6,3) V16(-5,3) V17(-4,3) V18(-3,3) V19(-2,3) V20(-1,3) V21(0,3) V22(1,3) V23(2,3) V24(3,3) V25(4,3) V26(5,3) V27(6,3) V28(7,3) V29(8,3) V30(9,3) V31(10,3) V32(11,3) V33(12,3) V34(13,3) V35(14,3) V36(15,3) V37(16,3) V38(17,3) V39(18,3) V40(19,3) V41(20,3) W1(-20,2) W2(-19,2) W3(-18,2) W4(-17,2) W5(-16,2) W6(-15,2) W7(-14,2) W8(-13,2) W9(-12,2) W10(-11,2) W11(-10,2) W12(-9,2) W13(-8,2) W14(-7,2) W15(-6,2) W16(-5,2) W17(-4,2) W18(-3,2) W19(-2,2) W20(-1,2) W21(0,2) W22(1,2) W23(2,2) W24(3,2) W25(4,2) W26(5,2) W27(6,2) W28(7,2) W29(8,2) W30(9,2) W31(10,2) W32(11,2) W33(12,2) W34(13,2) W35(14,2) W36(15,2) W37(16,2) W38(17,2) W39(18,2) W40(19,2) W41(20,2) Y1(-20,1) Y2(-19,1) Y3(-18,1) Y4(-17,1) Y5(-16,1) Y6(-15,1) Y7(-14,1) Y8(-13,1) Y9(-12,1) Y10(-11,1) Y11(-10,1) Y12(-9,1) Y13(-8,1) Y14(-7,1) Y15(-6,1) Y16(-5,1) Y17(-4,1) Y18(-3,1) Y19(-2,1) Y20(-1,1) Y21(0,1) Y22(1,1) Y23(2,1) Y24(3,1) Y25(4,1) Y26(5,1) Y27(6,1) Y28(7,1) Y29(8,1) Y30(9,1) Y31(10,1) Y32(11,1) Y33(12,1) Y34(13,1) Y35(14,1) Y36(15,1) Y37(16,1) Y38(17,1) Y39(18,1) Y40(19,1) Y41(20,1)
Top Overlay:
  circle w0.25: c-21.9,20 r0.125
  region: -20.25,21.25 -21.25,20.25 -21.25,21.25
  lines w0.2: -21.25,20.25 -20.25,21.25 ; -21.25,-21.25 -21.25,21.25 21.25,21.25 21.25,-21.25 -21.25,-21.25
Mechanical 13:
  lines w0.1: -21.25,-21.25 -21.25,21.25 21.25,21.25 21.25,-21.25 -21.25,-21.25
Mechanical 15:
  lines w0.1: -0.5,0 0.5,0 ; 0,-0.5 0,0.5 ; -22.25,-22.25 -22.25,22.25 22.25,22.25 22.25,-22.25 -22.25,-22.25
3D body: height 0, standoff 0, extent -21.25,-21.25 21.25,21.25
